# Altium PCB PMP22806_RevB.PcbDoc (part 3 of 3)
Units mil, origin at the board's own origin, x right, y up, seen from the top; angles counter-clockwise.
Board outline 5500 x 3040 mil, 4 copper layers (Top Layer, Signal Layer 1, Signal Layer 2, Bottom Layer), stack 61.2 mil thick; 196 components, 100 nets, 518 pads, 186 vias.
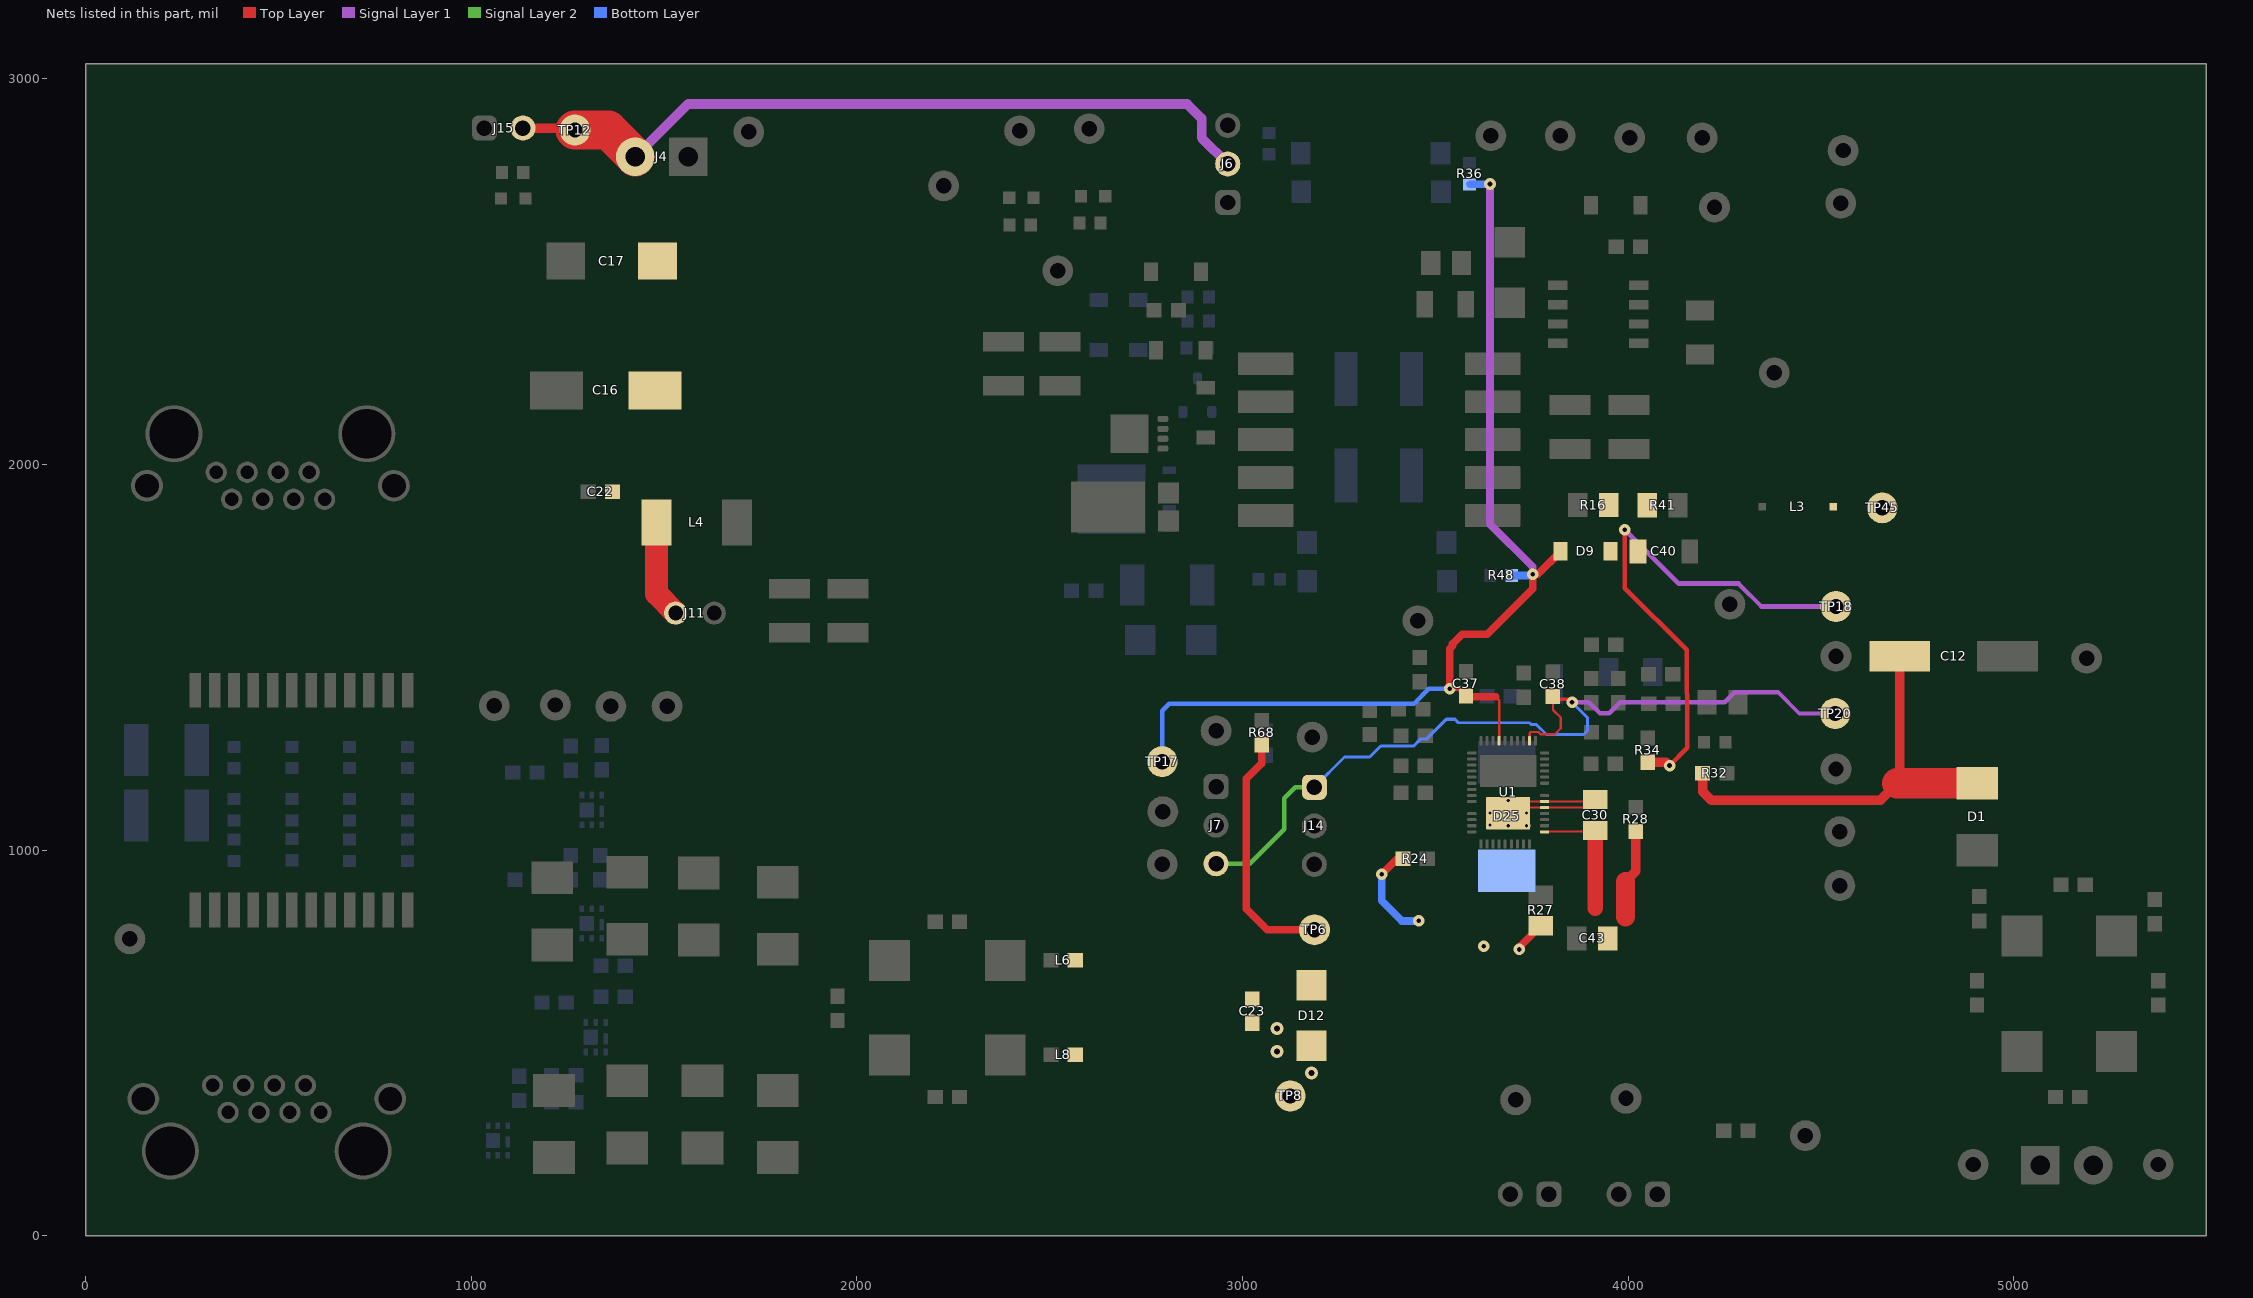
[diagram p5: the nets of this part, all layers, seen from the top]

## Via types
v1: diameter 30, hole 12, Top Layer to Bottom Layer, 104 vias
v2: diameter 34, hole 16, Top Layer to Bottom Layer, 37 vias
v3: diameter 30, hole 12, Top Layer to Bottom Layer, tented both sides, 22 vias
v4: diameter 19.68, hole 7.87, Top Layer to Bottom Layer, 19 vias
v5: diameter 20, hole 8, Top Layer to Bottom Layer, 2 vias
v6: diameter 26, hole 9, Top Layer to Bottom Layer, tented both sides, 1 vias
v7: diameter 19.68, hole 7.87, Top Layer to Bottom Layer, tented both sides, 1 vias

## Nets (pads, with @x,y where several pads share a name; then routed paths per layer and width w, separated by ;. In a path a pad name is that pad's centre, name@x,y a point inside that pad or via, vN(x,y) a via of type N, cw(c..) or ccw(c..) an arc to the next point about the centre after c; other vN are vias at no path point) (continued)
VB: C38.2 J7.3 J14.1 TP20.1 U1.37 | length 2263
  Top Layer w6: U1.37@3744.46,1283.91 3745.39,1284.85 3745.39,1303.68 3748.3,1306.59 3767.49,1306.59 3773.25,1300.83 3810.28,1300.83 3825.44,1315.99 3825.44,1343.93 3805.54,1363.83 C38.2@3805.54,1391.5
  Top Layer w10: C38.2@3805.54,1391.5 3846.95,1391.5 v3(3854.83,1383.63)
  Signal Layer 1 w10: 4388.43,1409.85 4443.86,1354.42 TP20.1@4537.31,1354.42
  Signal Layer 1 w12: v3(3854.83,1383.63) 3898.39,1383.63 3927.26,1354.75 3951.18,1354.75 3980.05,1383.63 4250.83,1383.63 4277.05,1409.85 4388.43,1409.85
  Signal Layer 2 w12: J7.3@2931.67,964.8 3018.64,964.8 3108.02,1054.18 3108.02,1134.54 3136.63,1163.15 J14.1@3186.48,1163.15
  Bottom Layer w8: J14.1@3186.48,1163.15 3264.83,1241.5 3330.01,1241.5 3358.87,1270.36 3444.4,1270.36 3462.9,1288.85 3478.04,1288.85 3528.87,1339.68 3551.13,1339.68 3560.13,1330.68 3745,1330 3749.26,1325.74 3762.53,1325.74 3788.43,1299.83 3884.83,1299.83 3895,1310 3895,1343.45 v3(3854.83,1383.63)
VCC: C37.1 D9.1 R36.2 R48.2 TP17.1 U1.42 | length 2853
  Top Layer w6: 3656.26,1398.28 3665.72,1388.83 U1.42@3665.72,1283.91
  Top Layer w12: v3(3537.45,1418.48) 3561.52,1418.48 C37.1@3579.75,1400.25
  Top Layer w20: v3(3537.45,1418.48) 3537.45,1522.61 3545.07,1530.23 3545.07,1535.13 3569.82,1559.87 3634.87,1559.87 3753.14,1678.14 v3(3753.14,1715.41) 3766.01,1715.41 D9.1@3825.31,1774.71 ; C37.1@3579.75,1400.25 3581.72,1398.28 3656.26,1398.28
  Signal Layer 1 w20: v1(3642.09,2727.61) 3642.09,1845.74 3753.14,1734.69 v3(3753.14,1715.41)
  Bottom Layer w12: TP17.1@2804.85,1242.61 TP17.1@2792.1,1229.86 2792.1,1362.1 2810,1380 3445,1380 3483.48,1418.48 v3(3537.45,1418.48)
  Bottom Layer w20: R36.2@3589.22,2726.7 3641.18,2726.7 v1(3642.09,2727.61) ; R48.2@3698.32,1712.61 3750.35,1712.61 v3(3753.14,1715.41)
VDD: C12.1 C23.1 C30.1 C43.1 D1.1 D12.1 L3.1 L6.2 R28.1 R32.2 R68.1 TP6.1 TP45.1 U1.23 | length 2325.8
  Top Layer w6: U1.23@3783.83,1047.69 3784.76,1048.63 3912.12,1048.63 C30.1@3914.73,1051.24
  Top Layer w20: R68.1@3050,1273.5 3050,1225 3010,1185 3010,848.34 3064.84,793.5 TP6.1@3186.99,793.5
  Top Layer w25: 3993.43,918.95 4019.73,945.25 R28.1@4019.73,1048.16 ; R32.2@4193.5,1200 4193.5,1151.87 4215.54,1129.83 4654.94,1129.83 4689.22,1164.11 ; 4698.79,1173.68 4704.46,1179.35 C12.1@4704.46,1502.61
  Top Layer w40: C30.1@3914.73,1051.24 3915,849.65
  Top Layer w50: 3993.43,827.48 3993.43,918.95 ; 4689.22,1164.11 4698.79,1173.68
  Top Layer w80: 4698.79,1173.68 D1.1@4905.66,1173.68
VOUT: C16.1 C17.1 C22.1 J4.2 J6.2 J11.2 J15.2 L4.2 TP12.1 | length 2265.2
  Top Layer w25: J15.2@1134.22,2872.61 1264.22,2872.61 TP12.1@1269.22,2867.61
  Top Layer w60: L4.2@1480.67,1850 1480.67,1664.65 J11.2@1530.32,1615
  Top Layer w100: TP12.1@1269.22,2867.61 1355.21,2867.61 J4.2@1425.21,2797.61
  Signal Layer 1 w25: J4.2@1425.21,2797.61 1562.71,2935.11 2856.72,2935.11 2894.22,2897.61 2894.22,2847.44 J6.2@2962.05,2779.62
VREG: C40.1 D9.2 R16.1 R34.1 R41.2 TP18.1 | length 1377.5
  Top Layer w12: v1(3991.82,1831.4) 3991.82,1679.55 4151.79,1519.57 4151.79,1407.73 4153.98,1405.55 4153.98,1265.89 v1(4107.62,1219.53)
  Top Layer w25: R41.2@4049.32,1895.16 R41.2@4049.78,1894.71 ; R34.1@4050.71,1227.93 v1@4099.23,1227.93
  Signal Layer 1 w12: v1(3991.82,1831.4) 4131.73,1691.48 4286.53,1691.48 4346.1,1631.92 TP18.1@4539.31,1631.92
VSS: C23.2 C30.2 D12.2 D25.2 L8.2 R24.1 R27.1 TP8.1 U1.27 U1.28 U1.47 | length 795
  Top Layer w6: v4(3689.34,1095.92) U1.47@3704.1,1110.68 ; C30.2@3914.73,1131.24 C30.2@3909.92,1126.43 ; U1.47@3704.1,1110.68 3719.85,1126.43 U1.28@3783.83,1126.43 C30.2@3909.92,1126.43 ; U1.47@3704.1,1110.68 U1.27@3783.83,1110.68 3894.17,1110.68 C30.2@3909.92,1126.43
  Top Layer w20: v1(3361.33,937.61) 3401.33,977.61 R24.1@3416.2,977.61 ; v1(3717.88,742.61) 3717.88,748.4 R27.1@3773.43,803.95
  Bottom Layer w20: v1(3361.33,937.61) 3361.33,868.67 3413.33,816.67 v1(3457.66,816.67)
  other v2: 3179.22,421.88 3089.85,478.14 3089.85,537.64
  other v3: 3626.1,750.55
  other v4: 3689.34,1063.44 3642.09,1095.92 3736.58,1095.92 3689.34,1128.4
  other v5: 3736.58,1063.44 3642.09,1065.07
pads on no net: Q3.9@2644.92,1852.91 Q3.9@2644.92,1910 Q3.9@2644.92,1967.09 Q3.9@2678.39,1910 Q3.9@2715,1852.91 Q3.9@2715,1910 Q3.9@2715,1967.09 Q4.0 Q5.0 Q6.0 Q7.0 Q10.9A Q10.9B Q10.9C Q10.9D T2.5 U1.6 U1.10 U1.12 U1.15 U1.16 U1.18 U1.19 U1.20 U1.22 U1.25 U1.26 U1.29 U1.30 U1.31 U1.41
copper on no net: | length 41.8
  Top Layer w6: 3680.53,1015.26 3681.46,1016.19 ; 3696.27,1015.26 3697.21,1016.19 ; 3783.83,1173.67 3797.77,1173.67 3812.09,1159.35 3817.01,1159.35

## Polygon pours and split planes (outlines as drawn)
PGND on Top Layer "TOP_LAYER_PGND_P344" (solid, remove dead copper, pour order 344): 3400,2970 3400,1585 3185,1370 2550,1370 2550,50 4810,50 4810,855 5420,855 5420,2970
NetQ2_1 on Top Layer "TOP_LAYER_NETQ2_1_P342" (solid, remove dead copper, pour order 342): 4000,2285 4000,2430 4235,2430 4235,2365 4140,2365 4100,2325 4100,2285
NetD7_2 on Top Layer "TOP_LAYER_NETD7_2_P340" (solid, remove dead copper, pour order 340): 3575,2230 3970,2230 3970,2500 3650,2500 3650,2300 3575,2300
NetC11_2 on Top Layer "TOP_LAYER_NETC11_2_P338" (solid, remove dead copper, pour order 338): 3550,2200 3550,2300 3400,2300 3400,2125 4135,2125 4250,2010 4250,1770 4410,1770 4410,2200
NetL6_1 on Top Layer "TOP_LAYER_NETL6_1_P330" (solid, remove dead copper, pour order 330): 2250,775 2250,860 2520,860 2520,660 2330,660 2330,775
NetL7_4 on Top Layer "TOP_LAYER_NETL7_4_P328" (solid, remove dead copper, pour order 328): 2250,300 2250,400 2330,400 2330,525 2520,525 2520,300
NetC7_1 on Top Layer "TOP_LAYER_NETC7_1_P326" (solid, remove dead copper, pour order 326): 4990,120 4990,330 4880,330 4880,615 4950,615 4950,535 5080,535 5080,400 5125,400 5125,120
NetC7_2 on Top Layer "TOP_LAYER_NETC7_2_P324" (solid, remove dead copper, pour order 324): 5285,120 5285,330 5405,330 5405,615 5335,615 5335,535 5210,535 5210,400 5150,400 5150,120
NetL2_4 on Top Layer "TOP_LAYER_NETL2_4_P322" (solid, remove dead copper, pour order 322): 5210,720 5210,835 5405,835 5405,640 5335,640 5335,720
NetL1_1 on Top Layer "TOP_LAYER_NETL1_1_P320" (solid, remove dead copper, pour order 320): 5080,720 4950,720 4950,640 4880,640 4880,835 5080,835
VDD on Top Layer "TOP_LAYER_VDD_P126" (solid, remove dead copper, pour order 126): 4470,860 4470,2970 4809.43,2970 4809.43,860 4809.43,600 2550,600 2550,860
NetC8_1 on Top Layer "TOP_LAYER_NETC8_1_P278" (solid, remove dead copper, pour order 278): 5140,1045 4850,1045 4850,855 5140,855
GND on Top Layer "TOP_LAYER_GND_P260" (solid, remove dead copper, pour order 260): 1105,2970 1105,1481.61 3160,1480 3305,1625 3305,2970
NetC18_1 on Top Layer "TOP_LAYER_NETC18_1_P258" (solid, remove dead copper, pour order 258): 1720,1620 1720,1570 1595,1570 1595,2265 2755,2265 2755,1620
VOUT on Top Layer "TOP_LAYER_VOUT_P250" (solid, remove dead copper, pour order 250): 1570,2680 1485,2680 1485,2970 1349.84,2970 1349.84,1695 1570,1695
no net on Top Layer "TOP_LAYER_NONET_P242" (solid, remove dead copper, pour order 242): 2845.36,2007.61
NetD18_1 on Top Layer "TOP_LAYER_NETD18_1_P240" (solid, remove dead copper, pour order 240): 2785,1930 2785,1805 2950,1805 2950,1930 3175.61,1930 3175.37,2093.98 2785,2093.98
VREG on Top Layer "TOP_LAYER_VREG_P238" (solid, remove dead copper, pour order 238): 3925,1930 3925,1740 4075,1740 4075,1930
CP on Top Layer "TOP_LAYER_CP_P236" (solid, remove dead copper, pour order 236): 3647.16,2092.61 3569.22,2092.61 3554.22,2107.61 3522.98,2107.61 3522.98,2032.44 3527.81,2027.61 3559.22,2027.61 3569.22,2037.61 3648.59,2037.61 3649.11,2038.13 3647.4,2039.84 3647.4,2090.74
no net on Top Layer "TOP_LAYER_NONET_P222" (solid, remove dead copper, pour order 222): 4214.22,2087.61
no net on Top Layer "TOP_LAYER_NONET_P218" (solid, remove dead copper, pour order 218): 3504.22,2217.81
no net on Top Layer "TOP_LAYER_NONET_P216" (solid, remove dead copper, pour order 216): 3482.21,2222.18
no net on Top Layer "TOP_LAYER_NONET_P212" (solid, remove dead copper, pour order 212): 3747.92,2179.9
VSS on Top Layer "TOP_LAYER_VSS_P208" (solid, remove dead copper, pour order 208): 3340,568.76 3340,1010 3444.22,1010 3444.22,1138.96 3810,1139.03 3810,300 3003.88,300 3003.88,568.76
no net on Top Layer "TOP_LAYER_NONET_P198" (solid, remove dead copper, pour order 198): 2173.98,375
no net on Top Layer "TOP_LAYER_NONET_P196" (solid, remove dead copper, pour order 196): 2294.04,205
NetC9_1 on Top Layer "TOP_LAYER_NETC9_1_P190" (solid, remove dead copper, pour order 190): 2220,775 2140,775 2140,660 2000,660 2000,600 1915,600 1915,855 1715,855 1715,1025 1288.5,1025 1290,1023.5 1290,855 1130,855 1130,1085 2220,1085
VSS on Top Layer "TOP_LAYER_VSS_P182" (solid, remove dead copper, pour order 182): 2550,570.6 2550,300 3229.22,300 3229.22,570.6
NetC9_2 on Top Layer "TOP_LAYER_NETC9_2_P132" (solid, remove dead copper, pour order 132): 2225,400 2140,400 2140,525 2000,525 2000,580 1915,580 1915,300 1715,300 1715,150 1295,150 1295,300 1135,300 1136.5,298.5 1136.5,50 2225,50
no net on Top Layer "TOP_LAYER_NONET_P124" (solid, remove dead copper, pour order 124): 2018.21,1012.27
NetC9_1 on Top Layer "TOP_LAYER_NETC9_1_P104" (solid, remove dead copper, pour order 104): 1350,181 1655,181 1655,315 1350,315
NetC9_2 on Top Layer "TOP_LAYER_NETC9_2_P102" (solid, remove dead copper, pour order 102): 1350,855 1645,855 1645,993.76 1350,993.76
PR45 on Top Layer "TOP_LAYER_PR45_P100" (solid, remove dead copper, pour order 100): 1535,511.08 1535,360 1850,360 1850,511.08
PR36 on Top Layer "TOP_LAYER_PR36_P098" (solid, remove dead copper, pour order 98): 1535,811.08 1535,635 1850,635 1850,811.08
BSP on Top Layer "TOP_LAYER_BSP_P094" (solid, remove dead copper, pour order 94): 950,2245.29 950,45.29 50,45.29 50,2245.29
PR12 on Top Layer "TOP_LAYER_PR12_P010" (solid, remove dead copper, pour order 10): 1455,790 1455,705 900,705 900,790
PR36 on Top Layer "TOP_LAYER_PR36_P008" (solid, remove dead copper, pour order 8): 1850,590 900,590 900,680 1850,680
PR45 on Top Layer "TOP_LAYER_PR45_P006" (solid, remove dead copper, pour order 6): 1850,470 900,470 900,560 1850,560
PR78 on Top Layer "TOP_LAYER_PR78_P004" (solid, remove dead copper, pour order 4): 1455,360 900,360 900,445 1455,445
no net on Top Layer "TOP_LAYER_NONET_P002" (solid, remove dead copper, pour order 2): 885,370
PGND on Bottom Layer "BOTTOM_LAYER_PGND_P316" (solid, remove dead copper, pour order 316): 2550,50 2550,1370 3185,1370 3399.98,1585 3399.98,2970.02 4810,2970.02 5420,2970 5420,855 4809.43,855 4810,50
GND on Bottom Layer "BOTTOM_LAYER_GND_P314" (solid, remove dead copper, pour order 314): 3305,2970 3305,1625 3160,1480 1104.97,1480 1105.94,2970
NetC18_1 on Bottom Layer "BOTTOM_LAYER_NETC18_1_P254" (solid, remove dead copper, pour order 254): 2500,2153.34 2500,1630.45 2765.94,1630.45 2765.94,2153.34
NetD18_1 on Bottom Layer "BOTTOM_LAYER_NETD18_1_P252" (solid, remove dead copper, pour order 252): 2782.17,2092.61 2782.16,1615.25 3179.22,1615.25 3179.22,2092.61
NetC11_2 on Bottom Layer "BOTTOM_LAYER_NETC11_2_P228" (solid, remove dead copper, pour order 228): 3400,2125 3400,2300 3550,2300 3550,2125
VSS on Bottom Layer "BOTTOM_LAYER_VSS_P202" (solid, remove dead copper, pour order 202): 3340,859.96 3340,1010 3585,1010 3585,1146.2 3810,1146.24 3810,300 2550.22,300 2548.91,861.49
NetC9_2 on Bottom Layer "BOTTOM_LAYER_NETC9_2_P172" (solid, remove dead copper, pour order 172): 1565,365 1460,365 1460,255 1107.75,255 1107.75,198.49 1565,198.49
NetC9_2 on Bottom Layer "BOTTOM_LAYER_NETC9_2_P168" (solid, remove dead copper, pour order 168): 1380,560 1380,346.26 2030,346.26 2030,560
BSP on Bottom Layer "BOTTOM_LAYER_BSP_P164" (solid, remove dead copper, pour order 164): 51.76,2245.62 951.76,2245.62 951.76,45.62 51.76,45.62
PR78 on Bottom Layer "BOTTOM_LAYER_PR78_P162" (solid, remove dead copper, pour order 162): 1060,440 1012.58,440 1012.58,200 1060,200
PR78 on Bottom Layer "BOTTOM_LAYER_PR78_P160" (solid, remove dead copper, pour order 160): 910,440 910,346.26 1050,346.26 1050,440
PR45 on Bottom Layer "BOTTOM_LAYER_PR45_P158" (solid, remove dead copper, pour order 158): 911.73,565 911.73,465 1315,465 1315,565
PR36 on Bottom Layer "BOTTOM_LAYER_PR36_P154" (solid, remove dead copper, pour order 154): 1135,775 1090,775 1090,670.29 911.73,670.29 911.73,615 1135,615
NetC9_2 on Bottom Layer "BOTTOM_LAYER_NETC9_2_P140" (solid, remove dead copper, pour order 140): 1380,1215 1620,1215 1620,454.76 1380,454.76
PR36 on Bottom Layer "BOTTOM_LAYER_PR36_P148" (solid, remove dead copper, pour order 148): 1090,855 1090,762.54 1305,762.54 1305,855
no net on Bottom Layer "BOTTOM_LAYER_NONET_P146" (solid, remove dead copper, pour order 146): 1354.34,1100
PR12 on Bottom Layer "BOTTOM_LAYER_PR12_P138" (solid, remove dead copper, pour order 138): 1010,1152.24 1065,1152.24 1065,729.71 1010,729.71
PR12 on Bottom Layer "BOTTOM_LAYER_PR12_P136" (solid, remove dead copper, pour order 136): 1010,1151.44 1010,1051.47 1300.2,1051.47 1300.2,1151.44
NetC11_2 on Signal Layer 1 "SIGNAL_LAYER_1_NETC11_2_P224" (solid, remove dead copper, pour order 224): 3495,2125 3495,2300 3550,2300 3550,2125
PGND on Signal Layer 1 "SIGNAL_LAYER_1_PGND_P336" (solid, remove dead copper, pour order 336): 2550,50 2550,1370 3185,1370 3400,1585 3400,2970 5420,2970 5420,855 4810,855 4810,50
GND on Signal Layer 1 "SIGNAL_LAYER_1_GND_P332" (solid, remove dead copper, pour order 332): 3305,2970 3305,1625 3160,1480 1105,1480 1105,2970
NetC18_1 on Signal Layer 1 "SIGNAL_LAYER_1_NETC18_1_P266" (solid, remove dead copper, pour order 266): 1720,1620 1720,1570 1595,1570 1595,2265 1600,2265 2755,2265 2755,1620
VSS on Signal Layer 1 "SIGNAL_LAYER_1_VSS_P200" (solid, remove dead copper, pour order 200): 3340,860 3340,1010 3585,1010 3585,1144.97 3810,1145.01 3810,300 2550,300 2550,860
NetC9_1 on Signal Layer 1 "SIGNAL_LAYER_1_NETC9_1_P180" (solid, remove dead copper, pour order 180): 1381.46,743.7 1378.5,740.74 1378.5,625.21 2037.96,625.21 2038.17,625 2038.17,747.03 1380,747.03
no net on Signal Layer 1 "SIGNAL_LAYER_1_NONET_P178" (solid, remove dead copper, pour order 178): 1493.58,580.25
no net on Signal Layer 1 "SIGNAL_LAYER_1_NONET_P176" (solid, remove dead copper, pour order 176): 1493.58,580.25
NetC9_1 on Signal Layer 1 "SIGNAL_LAYER_1_NETC9_1_P174" (solid, remove dead copper, pour order 174): 1380,728.54 1381.46,730 1645,730 1645,268.75 1380,268.75
PGND on Signal Layer 2 "SIGNAL_LAYER_2_PGND_P334" (solid, remove dead copper, pour order 334): 3400,2970 5420,2970 5420,855 4810,855 4810,50 2550,50 2550,1370 3185,1370 3400,1585
GND on Signal Layer 2 "SIGNAL_LAYER_2_GND_P262" (solid, remove dead copper, pour order 262): 1105,2970 1105,1480 3160,1480 3305,1625 3305,2970
NetC11_2 on Signal Layer 2 "SIGNAL_LAYER_2_NETC11_2_P226" (solid, remove dead copper, pour order 226): 3400,2125 3400,2300 3550,2300 3550,2125
VSS on Signal Layer 2 "SIGNAL_LAYER_2_VSS_P206" (solid, remove dead copper, pour order 206): 3340,860 2550,860 2550,300 3810,300 3810,1145.18 3585,1145.18 3585,1010 3340,1010

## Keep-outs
Keep-Out Layer:
  text ".Layer_Name" at 577,-858.49 h60

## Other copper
Top Layer:
  rectangle: 3809.56,1155.52 3851.42,1173
  text ".Layer_Name" at 577,-858.49 h60
Bottom Layer:
  text ".Layer_Name" at 577,-858.49 h60

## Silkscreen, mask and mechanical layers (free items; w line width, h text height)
Top Overlay:
  lines w10: 4077.98,1199.44 4324.57,925 4324.22,925 4324.22,600.58 4301.25,600.58 4268.03,600.58
  text "'.PRJ_Number'.PCB_Rev" at 210,2580 h108.27
  text ".Layer_Name" at 577,-858.49 h60
Bottom Overlay:
  text ".Layer_Name" at 577,-858.49 h60
Top Paste:
  text ".Layer_Name" at 577,-858.49 h60
Bottom Paste:
  text ".Layer_Name" at 577,-858.49 h60
Top Solder:
  text ".Layer_Name" at 577,-858.49 h60
  text ".Layer_Name" at 577,-858.49 h60
Bottom Solder:
  text ".Layer_Name" at 577,-858.49 h60
Drill Guide:
  text ".Layer_Name" at 577,-858.49 h60
M1 Board Outline:
  the board outline again, w10
  text ".Layer_Name" at 577,-858.49 h60
M2 Board Dimensions:
  rectangle: 0,-275 125,-150
  rectangle: 125,-400 500,-275
  lines w7: 0,-275 1000,-275 ; 125,-400 125,-150 ; 250,-400 250,-150 ; 500,-400 500,-150 ; 750,-400 750,-150 ; 0,-400 1000,-400 1000,-150 0,-150 0,-400
  text ".Layer_Name" at 577,-858.49 h60
M3 3D STEP Top:
  text ".Layer_Name" at 577,-858.49 h60
M4 3D STEP Bottom:
  text ".Layer_Name" at 577,-858.49 h60
M5 Assembly Top:
  lines w10: -292,-930.17 6308,-930.17 ; -292,-726.83 6310,-726.83 ; -292,-523.5 -292,-1133.5 3713,-1133.5 6310,-1133.5 6310,-523.5 -291.5,-523.5 -291.5,-1133.5 1284,-1133.5 ; 2173,-1133.5 2173,-523.5 ; 3440,-726.83 3440,-523.5 ; 4280,-726.83 4280,-523.5 ; 4902,-1140 4902,-937.17
  text "COMPONENTS MARKED 'DNP' SHOULD NOT BE POPULATED." at 1153.5,-318.5 h60
  text "ASSEMBLY VARIANT:" at 1153,-434 h60
  text ".VariantName" at 2189,-434 h60
  text "PCB VIEWED FROM TOP SIDE" at -228.5,-655.67 h60
  text "BOARD #:" at 2248,-655.67 h60
  text ".PRJ_Number" at 2793.5,-655.67 h60
  text "REV:" at 3638,-655.67 h60
  text ".PCB_Rev" at 3929.5,-655.67 h60
  text "SVN REV:" at 4476,-655.67 h60
  text ".VersionControl_RevNumber" at 4982,-655.67 h60
  text "TID #:" at 2248,-859 h60
  text ".TID" at 2793.5,-859 h60
  text "PLOT NAME =" at -228.5,-1064.34 h60
  text ".plot_File_Name" at 577,-1064.34 h60
  text "GENERATED    :" at 2250,-1064.34 h60
  text ".Print_Date" at 3119.5,-1064.34 h60
  text ".Print_Time" at 3848.5,-1064.34 h60
  text "TEXAS INSTRUMENTS" at 5113,-1064.34 h60
M6 Assembly Bottom:
  lines w10: -292.5,-727.33 6309.5,-727.33 ; -290.5,-930.67 6309.5,-930.67 ; 1115.5,-1140.5 1115.5,-937.67 ; 1737.5,-727.33 1737.5,-524 ; 2577.5,-727.33 2577.5,-524 ; 3844.5,-1134 3844.5,-524 ; 4733.5,-1134 6309,-1134 6309,-524 -292.5,-524 -292.5,-1134 2304.5,-1134 6309.5,-1134 6309.5,-524
  text "COMPONENTS MARKED 'DNP' SHOULD NOT BE POPULATED." at 6102,-318 h60
  text ".VariantName" at 5058,-434 h60
  text "ASSEMBLY VARIANT:" at 6097,-434 h60
  text ".VersionControl_RevNumber" at 1035.5,-656.17 h60
  text "SVN REV:" at 1541.5,-656.17 h60
  text ".PCB_Rev" at 2088,-656.17 h60
  text "REV:" at 2379.5,-656.17 h60
  text ".PRJ_Number" at 3224,-656.17 h60
  text "BOARD #:" at 3769.5,-656.17 h60
  text "PCB VIEWED FROM BOTTOM SIDE" at 6246,-656.17 h60
  text ".TID" at 3224,-859.5 h60
  text "TID #:" at 3769.5,-859.5 h60
  text "TEXAS INSTRUMENTS" at 904.5,-1064.84 h60
  text ".Print_Time" at 2169,-1064.84 h60
  text ".Print_Date" at 2898,-1064.84 h60
  text "GENERATED    :" at 3767.5,-1064.84 h60
  text ".plot_File_Name" at 5440.5,-1064.84 h60
  text "PLOT NAME =" at 6246,-1064.84 h60
M9 Title Sheet:
  drawing of 57 lines, arcs and shapes, not listed
  text "1" at 739.84,8036.5 h70
  text "2" at 3235.5,8036.5 h70
  text "3" at 5724.84,8036.5 h70
  text "4" at 8231.51,8036.5 h70
  text "5" at 10730.5,8036.5 h70
  text "6" at 13235.5,8036.5 h70
  text "A" at -416.5,6893.5 h70
  text "A" at 14383.5,6893.5 h70
  text "B" at -416.5,4513.5 h70
  text "B" at 14383.5,4513.5 h70
  text "C" at -416.5,2138.5 h70
  text "C" at 14383.5,2138.5 h70
  text "PROJECT TITLE:" at 11343.5,277.5 h45
  text ".PRJ_Title" at 11393.5,144.17 h70
  text "DESIGNED FOR:" at 11343.5,-23.5 h45
  text ".PRJ_Customer" at 11393.5,-163.5 h70
  text "D" at -416.5,-231.5 h70
  text "D" at 14383.5,-231.5 h70
  text "FILE NAME:" at 11343.5,-323.5 h45
  text ".PCB_File_Name_No_Path" at 11393.5,-443.5 h70
  text "Texas Instruments (TI) and/or its licensors do not warrant the accuracy or completeness of this specification" at 6374,-605.34 h45
  text "ENGINEER:" at 11343.5,-613.5 h45
  text "LAYOUT BY:" at 12848.5,-613.5 h45
  text "or any information contained therein. TI and/or its licensors do not warrant that this design will meet" at 6329.01,-718 h45
  text ".PRJ_Engineer" at 11393.5,-768.49 h70
  text ".PCB_Layout" at 12899,-768.49 h70
  text "the specifications, will be suitable for your application or fit for any particular purpose, or will operate in" at 6329.01,-830.67 h45
  text ".Layer_Name" at 577,-858.49 h60
  text "ALTIUM DESIGNER VERSION:" at 12848.5,-923.5 h45
  text "an implementation. TI and/or its licensors do not warrant that the design is production worthy. You should" at 6329.01,-943.33 h45
  text "completely validate and test your design implementation to confirm the system functionality for your application." at 6374,-1056 h45
  text ".print_Scale" at 11393.5,-1056.83 h70
  text ".Application_BuildNumber" at 12899,-1056.83 h70
  text "1" at 739.84,-1263.5 h70
  text "2" at 3235.5,-1263.5 h70
  text "3" at 5724.84,-1263.5 h70
  text "4" at 8231.51,-1263.5 h70
  text "5" at 10730.5,-1263.5 h70
  text "6" at 13235.5,-1263.5 h70
M10 Fab Notes:
  drawing of 189 lines, arcs and shapes, not listed
  text "DESIGN INFORMATION" at 12382.02,6356.17 h60
  text "MIN. TRACK WIDTH:" at 11737.46,6224.05 h60
  text "6" at 12833.7,6224.05 h60
  text "MIL" at 12988.46,6224.05 h60
  text "MIN. CLEARANCE:" at 11737.46,6099.92 h60
  text "0.2" at 12773.7,6099.93 h60
  text "mm" at 12988.46,6099.92 h60
  text "MIN. VIA PAD SIZE:" at 11737.46,5975.8 h60
  text "20" at 12803.71,5975.8 h60
  text "MIL" at 12988.46,5975.8 h60
  text "0.05mm (2MIL)" at 12432.46,5845.9 h60
  text "MINIMUM ANNULAR RING" at 11408.23,5837.67 h60
  text "EXTERNAL" at 13140.46,5837.67 h60
  text "PER" at 11608.23,5727.55 h60
  text "IPC-D-275 CLASS 2 LEVEL C" at 11828.23,5727.54 h60
  text "MIL, HOLES" at 13316.46,5627.07 h60
  text "+/-" at 12924,5618.48 h60
  text "+/-" at 13778,5618.48 h60
  text "REGISTRATION TOLERANCES:" at 11408.23,5617.42 h60
  text "METAL" at 12608,5617.42 h60
  text "5" at 13184.2,5617.42 h60
  text "3" at 14017.2,5617.42 h60
  text "MIL" at 14133.46,5617.42 h60
  text "HOLE SIZE TOLERANCE (UNLESS OTHERWISE SPECIFIED):" at 11408.23,5519.1 h60
  text "+/-" at 13778,5516.23 h60
  text "3" at 14017.2,5515.17 h60
  text "MIL" at 14133.46,5515.17 h60
  text "MATERIAL:" at 11333.46,5377.52 h60
  text "FR-4 High Tg" at 12319.9,5249 h60
  text "X" at 12175.46,5241.01 h60
  text "FR-408" at 11754.46,5236.49 h60
  text "OTHER" at 13242.46,5236.49 h60
  text "62 MIL (1.6mm) +/-10%" at 12074.56,5093.46 h60
  text "X" at 11954.46,5091.01 h60
  text "THICKNESS:" at 11408.23,5085.24 h60
  text "OTHER" at 13359.46,5085.24 h60
  text "TOLERANCE:" at 11408.23,4946.92 h60
  text "X" at 12256.46,4946.92 h60
  text "ANSI IPC-6012 TYPE 3 CLASS 2" at 12434.48,4946.92 h60
  text "OTHER +/-" at 12434.46,4802.73 h60
  text "BOW & TWIST:" at 11408.23,4657.54 h60
  text "X" at 12256.46,4657.54 h60
  text "ANSI IPC-6012 TYPE 3 CLASS 2" at 12434.48,4657.54 h60
  text "OTHER +/-" at 12434.46,4510.85 h60
  text "DRILLING:" at 11333.46,4380.23 h60
  text "NC_DRILL FILES" at 13094.46,4275.04 h60
  text "REFERENCE:" at 11408.23,4271.1 h60
  text "X" at 12065.46,4271.01 h60
  text "AS SHOWN" at 12243.46,4271.1 h60
  text "X" at 12966.46,4271.1 h60
  text "OTHER" at 13392.46,4128.85 h60
  text "PTH COPPER THICKNESS:" at 11407.91,4125.32 h60
  text "X" at 12547.14,4125.32 h60
  text "20-30 um" at 12675.14,4125.32 h60
  text "BOARD FINISH:" at 11333.46,3977.73 h60
  text "SILKSCREEN:" at 11488.68,3867.6 h60
  text "X" at 12446.46,3867.6 h60
  text "TOP" at 12563.46,3867.6 h60
  text "X" at 12956.46,3867.6 h60
  text "BOTTOM" at 13074.46,3867.6 h60
  text "SILKSCREEN COLOR:" at 11488.68,3712.41 h60
  text "X" at 12445.46,3712.41 h60
  text "WHITE" at 12563.46,3712.41 h60
  text "OTHER" at 13074.46,3712.41 h60
  text "X" at 12576.46,3568.96 h60
  text "GREEN" at 12694.46,3568.96 h60
  text "OTHER" at 13312.46,3568.96 h60
  text "SOLDER RESIST COLOR:" at 11488.68,3562.1 h60
  text "MATTE" at 12694.46,3414.71 h60
  text "X" at 13165,3415 h60
  text "SEMI-GLOSS" at 13312,3414.07 h60
  text "IMMERSION GOLD (ENIG)" at 12394.46,3241.94 h60
  text "ENEPIG" at 13732,3234.72 h60
  text "SURFACE FINISH:" at 11333.46,3233.72 h60
  text "X" at 12216.46,3233.72 h60
  text "IMM. TIN/SILVER OR EQUIV" at 11663,3096.4 h60
  text "OTHER" at 13094.46,3092.47 h60
  text "ARRAY/PANEL:" at 11333.46,2937.09 h60
  text "X" at 12216.46,2935 h60
  text "CUT AND TRIM PER M1 BOARD OUTLINE" at 12394.46,2928.87 h60
  text "N.C. ROUTE" at 12394.46,2792.9 h60
  text "V. SCORE" at 13260.46,2792.9 h60
  text "CERTIFICATION:" at 11333.46,2663.77 h60
  text "MATERIALS AND WORKMANSHIP FOR ALL PCBS" at 12058.46,2663.77 h60
  text "TO MEET OR EXCEED THE REQUIREMENTS OF:" at 12058.46,2569.71 h60
  text "X" at 11695.97,2441.08 h60
  text "ANSI IPC-A-600F CLASS ->" at 11823.96,2441.08 h60
  text "X" at 13471.97,2441.08 h60
  text "2" at 13581.96,2441.08 h60
  text "1" at 13266.96,2439.58 h60
  text "3" at 13935.96,2439.58 h60
  text "X" at 12507.97,2293.39 h60
  text "RoHS" at 12635.96,2293.39 h60
  text "OTHER" at 13280.36,2293.39 h60
  text "PER ORDER" at 13677.42,2293.39 h60
  text "ALL BOARDS MUST MEET OR EXCEED UL94-V0 REQUIREMENTS." at 11361,2139.57 h60
  text "PCB MUST BEAR THE UL94V-0 UL REGISTERED MATERIAL ID NUMBER" at 11361,2023.5 h60
  text "ADDITIONAL REQUIREMENTS:" at 11333.46,1854.08 h60
  text "MICROSECTION:" at 11408.23,1746.95 h60
  text "YES" at 12313.96,1746.95 h60
  text "REQUIRED" at 13175.46,1602.62 h60
  text "BARE BOARD ELEC. TEST:" at 11408.23,1599.76 h60
  text "NONE" at 12713.96,1599.76 h60
  text "X" at 13057.46,1599.76 h60
  text "PER ORDER" at 13767.46,1599.76 h60
  text "XX MIL VIAS REQUIRE NON-CONDUCTIVE FILL AND PLANARIZE" at 11576.38,1394.82 h59
  text "XX MIL VIAS REQUIRE CONDUCTIVE FILL AND PLANARIZE" at 11584.38,1290.84 h60
  text "OUTER XX MIL TRACES REQUIRE 50 OHM SINGLE-ENDED IMPEDANCE" at 11583.39,1127.46 h58
  text "LAYER 2 & 3 (INNER LAYERS) XX MIL WIDE, XX MIL SPACE / TRACES REQUIRE 100 OHM DIFFERENTIAL IMPEDANCE" at 11575.39,891.74 h60
  text ".Layer_Name" at 577,-858.49 h60
M11 Gerber Information:
  lines w10: -292,-930.17 6308,-930.17 ; -292,-726.83 6310,-726.83 ; -292,-523.5 -292,-1133.5 3713,-1133.5 6310,-1133.5 6310,-523.5 -291.5,-523.5 -291.5,-1133.5 1284,-1133.5 ; 2173,-1133.5 2173,-523.5 ; 3440,-726.83 3440,-523.5 ; 4280,-726.83 4280,-523.5 ; 4902,-1140 4902,-937.17
  text "ALL ARTWORK VIEWED FROM TOP SIDE" at -228.5,-655.67 h60
  text "BOARD #:" at 2248,-655.67 h60
  text ".PRJ_Number" at 2793.5,-655.67 h60
  text "REV:" at 3638,-655.67 h60
  text ".PCB_Rev" at 3929.5,-655.67 h60
  text "SVN REV:" at 4476,-655.67 h60
  text ".VersionControl_RevNumber" at 4982,-655.67 h60
  text "LAYER NAME =" at -228.5,-858.49 h60
  text "TID #:" at 2248,-859 h60
  text ".TID" at 2793.5,-859 h60
  text "PLOT NAME =" at -228.5,-1064.34 h60
  text ".plot_File_Name" at 577,-1064.34 h60
  text "GENERATED    :" at 2250,-1064.34 h60
  text ".Print_Date" at 3119.5,-1064.34 h60
  text ".Print_Time" at 3848.5,-1064.34 h60
  text "TEXAS INSTRUMENTS" at 5113,-1064.34 h60
M12 Stackup:
  drawing of 295 lines, arcs and shapes, not listed
  text "Layer" at 9775.58,7830 h60
  text "Name" at 10185.49,7830 h60
  text "Material" at 11125.23,7830 h60
  text "Thickness" at 11985,7830 h60
  text "Constant" at 12634.84,7830 h60
  text "Board Layer Stack" at 13204.7,7830 h60
  text "1" at 9775.58,7710 h60
  text "Top Overlay" at 10185.49,7710 h60
  text "2" at 9775.58,7590 h60
  text "Top Solder" at 10185.49,7590 h60
  text "Solder Resist" at 11125.23,7590 h60
  text "0.40mil" at 11985,7590 h60
  text "3.5" at 12634.84,7590 h60
  text "3" at 9775.58,7470 h60
  text "Top Layer" at 10185.49,7470 h60
  text "Copper" at 11125.23,7470 h60
  text "2.80mil" at 11985,7470 h60
  text "4" at 9775.58,7350 h60
  text "Dielectric1" at 10185.49,7350 h60
  text "FR-4" at 11125.23,7350 h60
  text "15.00mil" at 11985,7350 h60
  text "4.8" at 12634.84,7350 h60
  text "5" at 9775.58,7230 h60
  text "Signal Layer 1" at 10185.49,7230 h60
  text "Copper" at 11125.23,7230 h60
  text "2.80mil" at 11985,7230 h60
  text "6" at 9775.58,7110 h60
  text "Dielectric 2" at 10185.49,7110 h60
  text "20.00mil" at 11985,7110 h60
  text "4.2" at 12634.84,7110 h60
  text "7" at 9775.58,6990 h60
  text "Signal Layer 2" at 10185.49,6990 h60
  text "Copper" at 11125.23,6990 h60
  text "2.80mil" at 11985,6990 h60
  text "8" at 9775.58,6870 h60
  text "Dielectric 3" at 10185.49,6870 h60
  text "15.00mil" at 11985,6870 h60
  text "4.2" at 12634.84,6870 h60
  text "9" at 9775.58,6750 h60
  text "Bottom Layer" at 10185.49,6750 h60
  text "Copper" at 11125.23,6750 h60
  text "2.80mil" at 11985,6750 h60
  text "10" at 9775.58,6630 h60
  text "Bottom Solder" at 10185.49,6630 h60
  text "Solder Resist" at 11125.23,6630 h60
  text "0.40mil" at 11985,6630 h60
  text "3.5" at 12634.84,6630 h60
  text "11" at 9775.58,6510 h60
  text "Bottom Overlay" at 10185.49,6510 h60
  text ".Layer_Name" at 577,-858.49 h60
M13 Component Bodies Top:
  text ".Layer_Name" at 577,-858.49 h60
M14 Component Bodies Bottom:
  text ".Layer_Name" at 577,-858.49 h60
M15 Courtyards Top:
  text ".Layer_Name" at 577,-858.49 h60
M16 Courtyards Bottom:
  text ".Layer_Name" at 577,-858.49 h60
Drill Drawing:
  circle w10: c5988.54,1120.57 r27.56
  lines w10: 5960.98,238.6 5974.76,238.6 5974.76,224.82 6002.32,224.82 6002.32,238.6 6016.1,238.6 6016.1,266.16 6002.32,266.16 6002.32,279.94 5974.76,279.94 5974.76,266.16 5960.98,266.16 5960.98,238.6 ; 5960.98,348.85 5988.54,362.63 6016.1,348.85 6002.32,376.41 6016.1,403.97 5988.54,390.19 5960.98,403.97 5974.76,376.41 5960.98,348.85 ; 5960.98,528 6016.1,528 5988.54,472.87 5960.98,528 ; 5960.98,610.68 5974.76,610.68 5988.54,596.9 6002.32,610.68 6016.1,610.68 6002.32,624.46 6016.1,638.24 6002.32,638.24 5988.54,652.02 5974.76,638.24 5960.98,638.24 5974.76,624.46 5960.98,610.68 ; 5960.98,776.05 6016.1,776.05 5988.54,720.93 5960.98,776.05 ; 5960.98,844.95 5960.98,858.73 5974.76,872.52 5960.98,886.3 5960.98,900.08 5974.76,900.08 5988.54,886.3 6002.32,900.08 6016.1,900.08 6016.1,886.3 6002.32,872.52 6016.1,858.73 6016.1,844.95 6002.32,844.95 5988.54,858.73 5974.76,844.95 5960.98,844.95 ; 5960.98,968.98 6016.1,968.98 6016.1,1024.1 5960.98,1024.1 5960.98,968.98 ; 5960.98,1217.03 5988.54,1230.81 6016.1,1217.03 6002.32,1244.6 6016.1,1272.16 5988.54,1258.38 5960.98,1272.16 5974.76,1244.6 5960.98,1217.03 ; 5960.98,1341.06 6016.1,1341.06 6016.1,1396.18 5960.98,1396.18 5960.98,1341.06 ; 5960.98,1492.65 5988.54,1465.09 6016.1,1492.65 5988.54,1520.21 5960.98,1492.65 ; 5972,765.03 6005.08,765.03 5988.54,731.95 5972,765.03 ; 5972,1228.06 5988.54,1236.33 6005.08,1228.06 5996.81,1244.6 6005.08,1261.13 5988.54,1252.86 5972,1261.13 5980.27,1244.6 5972,1228.06 ; 5972,1352.09 6005.08,1352.09 6005.08,1385.16 5972,1385.16 5972,1352.09
  lines w12: 5911,187.61 9137.8,187.61 ; 5911,1551.91 9137.8,1551.91 ; 6248.36,63.59 6248.36,1675.93 ; 6580.06,63.59 6580.06,1675.93 ; 7215.91,63.59 7215.91,1675.93 ; 7474.71,63.59 7474.71,1675.93 ; 7849.46,63.59 7849.46,1675.93 ; 8572,63.59 8572,1675.93 ; 5911,63.59 9137.8,63.59 9137.8,1675.93 5911,1675.93 5911,63.59
  text "Symbol" at 5985.42,1589.11 h72
  text "Quantity" at 6285.57,1589.11 h72
  text "Finished Hole Size" at 6617.26,1589.11 h72
  text "Plated" at 7253.12,1589.11 h72
  text "Hole Type" at 7511.92,1589.11 h72
  text "Drill Layer Pair" at 7886.67,1589.11 h72
  text "Hole Tolerance" at 8609.21,1589.11 h72
  text "20" at 6285.57,1465.09 h60
  text "7.87mil (0.200mm)" at 6617.26,1465.09 h60
  text "PTH" at 7253.12,1465.09 h60
  text "Round" at 7511.92,1465.09 h60
  text "Top Layer - Bottom Layer" at 7886.67,1465.09 h60
  text "2" at 6285.57,1341.06 h60
  text "8.00mil (0.203mm)" at 6617.26,1341.06 h60
  text "PTH" at 7253.12,1341.06 h60
  text "Round" at 7511.92,1341.06 h60
  text "Top Layer - Bottom Layer" at 7886.67,1341.06 h60
  text "1" at 6285.57,1217.03 h60
  text "9.00mil (0.229mm)" at 6617.26,1217.03 h60
  text "PTH" at 7253.12,1217.03 h60
  text "Round" at 7511.92,1217.03 h60
  text "Top Layer - Bottom Layer" at 7886.67,1217.03 h60
  text "126" at 6285.57,1093.01 h60
  text "12.00mil (0.305mm)" at 6617.26,1093.01 h60
  text "PTH" at 7253.12,1093.01 h60
  text "Round" at 7511.92,1093.01 h60
  text "Top Layer - Bottom Layer" at 7886.67,1093.01 h60
  text "37" at 6285.57,968.98 h60
  text "16.00mil (0.406mm)" at 6617.26,968.98 h60
  text "PTH" at 7253.12,968.98 h60
  text "Round" at 7511.92,968.98 h60
  text "Top Layer - Bottom Layer" at 7886.67,968.98 h60
  text "16" at 6285.57,844.95 h60
  text "35.04mil (0.890mm)" at 6617.26,844.95 h60
  text "PTH" at 7253.12,844.95 h60
  text "Round" at 7511.92,844.95 h60
  text "Top Layer - Bottom Layer" at 7886.67,844.95 h60
  text "2" at 6285.57,720.93 h60
  text "38.00mil (0.965mm)" at 6617.26,720.93 h60
  text "PTH" at 7253.12,720.93 h60
  text "Round" at 7511.92,720.93 h60
  text "Top Layer - Bottom Layer" at 7886.67,720.93 h60
  text "56" at 6285.57,596.9 h60
  text "40.00mil (1.016mm)" at 6617.26,596.9 h60
  text "PTH" at 7253.12,596.9 h60
  text "Round" at 7511.92,596.9 h60
  text "Top Layer - Bottom Layer" at 7886.67,596.9 h60
  text "4" at 6285.57,472.87 h60
  text "50.00mil (1.270mm)" at 6617.26,472.87 h60
  text "PTH" at 7253.12,472.87 h60
  text "Round" at 7511.92,472.87 h60
  text "Top Layer - Bottom Layer" at 7886.67,472.87 h60
  text "4" at 6285.57,348.85 h60
  text "61.81mil (1.570mm)" at 6617.26,348.85 h60
  text "PTH" at 7253.12,348.85 h60
  text "Round" at 7511.92,348.85 h60
  text "Top Layer - Bottom Layer" at 7886.67,348.85 h60
  text "4" at 6285.57,224.82 h60
  text "128.00mil (3.251mm)" at 6617.26,224.82 h60
  text "PTH" at 7253.12,224.82 h60
  text "Round" at 7511.92,224.82 h60
  text "Top Layer - Bottom Layer" at 7886.67,224.82 h60
  text "272 Total" at 6285.57,100.79 h60
  text ".Layer_Name" at 577,-858.49 h60
M17 Embedded Cavity:
  text ".Layer_Name" at 577,-858.49 h60
M18 Embedded Assembly:
  text ".Layer_Name" at 577,-858.49 h60
M19 Embedded Keepout:
  text ".Layer_Name" at 577,-858.49 h60

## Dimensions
0,-400 to 1000,-400 on M2 Board Dimensions
0,0 to 0,3040 on M2 Board Dimensions
0,0 to 5500,0 on M2 Board Dimensions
